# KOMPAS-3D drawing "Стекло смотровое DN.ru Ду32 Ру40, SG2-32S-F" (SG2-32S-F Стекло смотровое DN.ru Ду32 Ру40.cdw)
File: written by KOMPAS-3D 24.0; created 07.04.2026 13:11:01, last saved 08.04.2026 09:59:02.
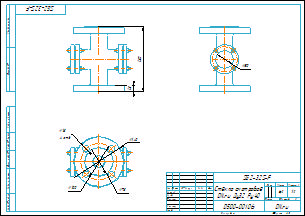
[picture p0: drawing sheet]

Document properties: Автор: Main; Форматы листов документа: A3; Полное имя файла: SG2-32S-F Стекло смотровое DN.ru Ду32 Ру40.m3d; Масса: 6.2; Наименование: Стекло смотровое DN.ru Ду32 Ру40; Количество листов документа: 1; Примечание: D500-00106

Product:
- Body: Тело 1  | qty 1
    Масса: 6.03947
- Part/product: Стекло смотровое DN.ru Ду32 Ру40  | designation SG2-32S-F
    Масса: 6.2
    Раздел спецификации: Прочие изделия
    Примечание: D500-00106

Views: Вид 1, Снизу, Проекционный вид 2
Referenced files in D:\DN.ru Аутсерс\Стекло смотровое DN.ru\Стекло смотровое DN.ru SG2-34G-F тип В ГОСТ 21836-2021 Ду100 Ру16, углеродистая сталь, фланцевое\: SG2-34G-F тип В Стекло смотровое DN.ru Ду100 Ру16.m3d, SG2-34G-F тип ВСтекло смотровое DN.ru Ду100 Ру16.cdw
Referenced files in D:\DN.ru Аутсерс\Стекло смотровое DN.ru\SG2-32S-F Стекло смотровое DN.ru Ду32 Ру40\: SG2-32S-F Стекло смотровое DN.ru Ду32 Ру40.m3d
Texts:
  SG2-32S-F
  Стекло смотровое
  DN.ru Ду32 Ру40
  Стекло смотровое DN.ru Ду32 Ру40
  SG2-32S-F Стекло смотровое DN.ru Ду32 Ру40
Dimensions and other numbers on the sheet: 0; 3; 2; 4; 180; 18; 4 отв.; 100; 78; 140; 1:2; 1; 6,2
